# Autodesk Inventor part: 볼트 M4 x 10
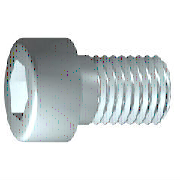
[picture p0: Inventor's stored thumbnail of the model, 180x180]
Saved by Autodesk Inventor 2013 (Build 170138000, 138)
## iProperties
IsCustomPart: 0
Created: 2012-02
Part Number: 볼트 M4 x 10
Material: 스테인리스강
Description: 6각 소켓 머리 캡 나사
Document SubType Name: Modeling
Standard: ISO 4762
Designer: mduedu
Standard Revision: Fourth edition 2004-03-01
Standards Organization: ISO
Language: ko-KR
Size Designation: M4 x 10
Categories: <MemberInstance><Categories><Category DisplayName="조임쇠" InternalName="e4da775c-781d-43d5-af7c-5136215cf5a6" Mnemonic="FSTN"><Category DisplayName="볼트" InternalN
Density: 8.08 g/cm^3
Mass: 2.09412 g
Surface Area: 3.0572 cm^2
Volume: 0.259174 cm^3
Author: mduedu
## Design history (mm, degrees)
sketch "스케치1"
  geometry: L1 (-1, 0)-(10, 0); L2 (10, 0)-(10, 2); L3 (10, 2)-(1.75, 2); L4 (1.75, 2)-(1.32, 2); L5 (1.32, 2)-(0, 2); L6 (0, 2)-(0, 3.5); L7 (0, 3.5)-(-4, 3.5); L8 (-4, 3.5)-(-4, 1.732); L9 (-4, 1.732)-(-2, 1.732); L10 (-2, 1.732)-(-1, 0); L11 (-6.8, 0)-(12.8, 0) reference; L12 (0, -0.7)-(0, 4.2) reference; L13 (1.75, 2)-(0, 2)
  constraints: 22 end point, 6 parallel, 2 collinear, 2 perpendicular, 1 horizontal, 1 point on line
  dimensions: "d1" = 8.25 distance from line of L3.end L2 (= GEL); "d2" = 0.42952 distance of L4.end L3.end (computed from GAL); "d3" = 4 distance between parallel lines of L8 L6 (= KOH); "d4" = 2 distance of L8.end L9.end (= INTI); "d5" = 60 deg angle of L10 L1; "d6" = 4 diameter of L3 L1 (= GD); "d7" = 4 diameter of L5 L1 (= BDM); "d8" = 3.4641 diameter of L9 L1 (= 1.1547 x SW); "d9" = 7 diameter of L7 L1 (= KOD); "d26" = 10 distance between parallel lines of L12 L2 (= NLG)
revolve "본체" sketch "스케치1" stored, may be unused: angle "d10" = 90 deg
sketch "스케치2"
  geometry: L1 (0, -4.9)-(0, 4.9) reference; L2 (-4.9, 0)-(4.9, 0) reference; L3 (1.732, 0)-(0.866, -1.5); L4 (0.866, -1.5)-(-0.866, -1.5); L5 (-0.866, -1.5)-(-1.732, 0); L6 (-1.732, 0)-(-0.866, 1.5); L7 (-0.866, 1.5)-(0.866, 1.5); L8 (0.866, 1.5)-(1.732, 0); 2 further points
  constraints: 12 end point, 1 coincident, 1 horizontal alignment, 1 point on line, 12 other
extrude "슬롯" join sketch "스케치2" stored distance "d11" = 10; taper "d12" = 0 deg
workplane "Work Plane1"
fillet "Fillet2" dims "d30" = 0.1 (= R)
body "Solid1"
fillet "모깎기1" dims "d17" = 0.4 (= RR)
feature "스레드" dims "d13" = 8.25 (= GEL), "d14" = 0
chamfer "모따기1" distance "d15" = 0.42941 (= -0.5 x SPD + 0.5 x GD); stored, may be unused: second distance "d16" = 0.42941 (= GUL), angle "d27" = 45 deg
other parameters: "GD" = 4 [user parameter; used in 2 equation terms], "NLG" = 10 [user parameter; used in 1 equation term], "GEL" = 8.25 [user parameter; used in 2 equation terms], "KOD" = 7 [user parameter; used in 1 equation term], "KOH" = 4 [user parameter; used in 1 equation term], "INTI" = 2 [user parameter; used in 1 equation term], "GAL" = 0.42941 (= 0.61345 x PTC) [user parameter; used in 1 equation term], "GUL" = 0.42941 (= 0.61345 x PTC) [user parameter; used in 1 equation term], "BDM" = 4 (= NND) [user parameter; used in 1 equation term], "SW" = 3 [user parameter; used in 2 equation terms], "RR" = 0.4 [user parameter; used in 1 equation term], "SPD" = 3.14117 (= NND - 1.2269 x PTC) [user parameter; used in 1 equation term], "d19" = 0, "d28" = 0, "d29" = 0, "R" = 0.1 [user parameter; used in 1 equation term], "TOA" = 30 deg [user parameter], "GD1" = 3.14117 (= THREADDIA - 1.2269 x PTC) [user parameter], "THREADDIA" = 4 [user parameter; used in 1 equation term], "FAWI" = 45 deg [user parameter], "TPU" = 14.28571 (computed from PTC) [user parameter], "PTC" = 0.7 [user parameter; used in 5 equation terms], "NND" = 4 [user parameter; used in 2 equation terms], "E0" = 3.465 (= 1.155 x SW) [user parameter]
